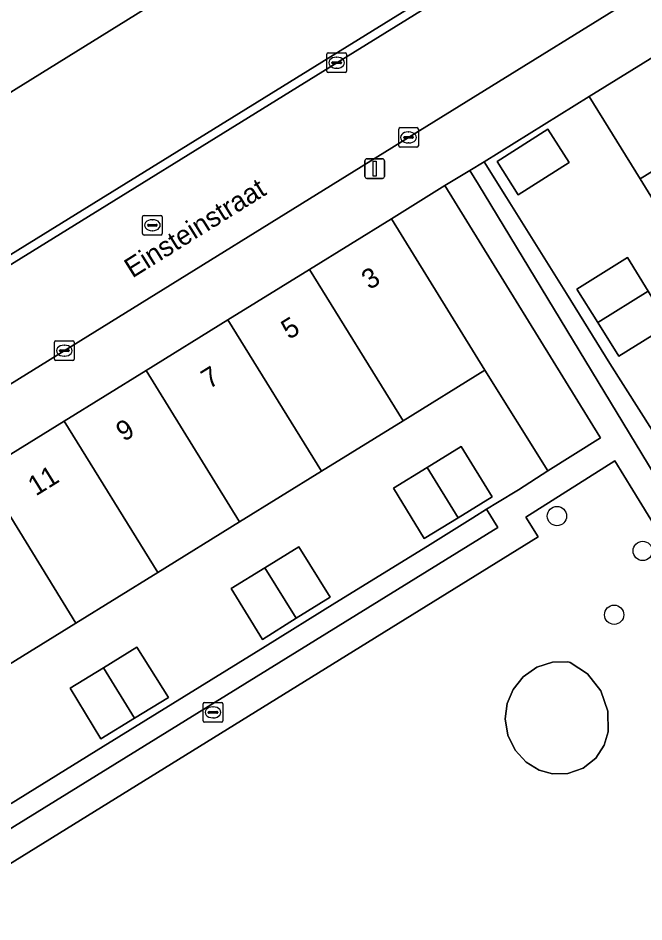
# Model space of a CAD drawing. Extents: x 159888 to 160761, y 384031 to 384750.
# Drawn here: x 160154.85 to 160186.63, y 384561.64 to 384607.52 of the extents above; entities that cross this region are included whole.
import ezdxf

# ---------------------------------------------------------------- set-up
doc = ezdxf.new("R2010")
doc.units = 0
for name, color, linetype in [('IMGEO_Boom', 7, 'Continuous'), ('IMGEO_Erf', 7, 'Continuous'), ('IMGEO_Groenvoorziening', 7, 'Continuous'), ('IMGEO_Kolk', 7, 'Continuous'), ('IMGEO_Lichtmast', 7, 'Continuous'), ('IMGEO_Openbare_ruimte_label', 7, 'Continuous'), ('IMGEO_Pand', 7, 'Continuous'), ('IMGEO_Pand_nummerreeks', 7, 'Continuous'), ('IMGEO_Rijbaan_lokaal_open', 7, 'Continuous'), ('IMGEO_Rioolput', 7, 'Continuous'), ('IMGEO_Terreindeel_onvherhard', 7, 'Continuous'), ('IMGEO_Voetpad_open', 7, 'Continuous')]:
    doc.layers.add(name, color=color, linetype=linetype)

msp = doc.modelspace()

# ---------------------------------------------------------------- linework, layer by layer
at = {"layer": 'IMGEO_Boom'}
for centre in [(160182.218, 384582.245), (160186.573, 384580.476), (160185.121, 384577.235)]:
    msp.add_circle(centre, 0.489, dxfattribs=at)
at = {"layer": 'IMGEO_Erf'}
for points in [[(160137.178, 384619.898), (160101.924, 384598.362), (160110.734, 384584.277), (160114.059, 384578.949), (160127.142, 384586.832), (160189.258, 384625.337)], [(160154.504, 384567.651), (160159.181, 384570.545), (160162.717, 384572.729), (160167.402, 384575.62), (160170.932, 384577.817), (160175.649, 384580.721), (160176.59, 384581.308), (160177.945, 384582.154), (160178.648, 384582.593), (160179.199, 384582.937), (160180.262, 384583.57), (160181.762, 384584.546), (160178.562, 384589.653), (160174.408, 384587.085), (160170.254, 384584.518), (160166.1, 384581.95), (160161.945, 384579.382), (160157.791, 384576.814), (160153.637, 384574.247)]]:
    msp.add_lwpolyline(points, dxfattribs=at)
for points in [[(160201.898, 384574.344), (160199.321, 384578.512), (160196.745, 384582.681), (160194.168, 384586.85), (160191.591, 384591.019), (160189.015, 384595.187), (160186.438, 384599.356), (160183.852, 384603.54), (160178.522, 384600.227), (160179.656, 384598.411), (160182.706, 384593.538), (160184.899, 384589.992), (160187.856, 384585.356), (160190.049, 384581.81), (160192.976, 384577.075), (160195.169, 384573.529), (160198.086, 384568.923), (160200.279, 384565.377), (160201.907, 384562.777), (160207.047, 384566.013), (160204.475, 384570.175)], [(160180.252, 384598.554), (160179.181, 384600.243), (160181.759, 384601.877), (160182.83, 384600.188)], [(160185.358, 384590.358), (160184.289, 384592.064), (160183.219, 384593.769), (160185.792, 384595.375), (160186.841, 384593.664), (160187.905, 384591.929)], [(160173.91, 384583.659), (160175.63, 384584.716), (160177.35, 384585.773), (160178.921, 384583.217), (160177.201, 384582.16), (160175.481, 384581.103)], [(160165.677, 384578.561), (160167.392, 384579.621), (160169.107, 384580.68), (160170.697, 384578.131), (160168.977, 384577.055), (160167.263, 384575.983)], [(160157.492, 384573.501), (160159.189, 384574.542), (160160.887, 384575.582), (160162.484, 384573.035), (160160.759, 384571.98), (160159.059, 384570.94)]]:
    msp.add_lwpolyline(points, close=True, dxfattribs=at)
at = {"layer": 'IMGEO_Groenvoorziening'}
for points in [[(160187.228, 384615.776), (160189.258, 384625.337), (160127.142, 384586.832), (160114.059, 384578.949), (160114.138, 384578.822), (160118.034, 384572.48), (160122.909, 384575.488), (160128.843, 384579.15), (160136.097, 384583.626), (160140.332, 384586.252), (160140.095, 384586.635)], [(160214.717, 384570.75), (160207.047, 384566.013), (160201.907, 384562.777), (160200.279, 384565.377), (160198.086, 384568.923), (160195.169, 384573.529), (160192.976, 384577.075), (160190.049, 384581.81), (160187.856, 384585.356), (160184.899, 384589.992), (160182.706, 384593.538), (160179.656, 384598.411), (160178.522, 384600.227), (160177.796, 384599.792), (160178.233, 384599.071), (160201.865, 384560.132), (160209.103, 384564.601), (160215.907, 384568.818)], [(160176.521, 384599.021), (160173.813, 384597.334), (160178.562, 384589.653), (160181.762, 384584.546), (160184.426, 384586.21), (160184.387, 384586.273)], [(160179.214, 384581.669), (160178.648, 384582.593), (160177.945, 384582.154), (160176.59, 384581.308), (160175.649, 384580.721), (160170.932, 384577.817), (160167.402, 384575.62), (160162.717, 384572.729), (160159.181, 384570.545), (160154.504, 384567.651), (160150.964, 384565.459), (160146.234, 384562.542), (160142.688, 384560.346), (160138.005, 384557.454), (160134.451, 384555.279), (160131.882, 384553.717), (160132.027, 384553.482), (160132.473, 384552.799), (160139.949, 384557.419)], [(160179.72, 384571.131), (160179.591, 384571.95), (160179.687, 384572.723), (160179.987, 384573.442), (160180.505, 384574.088), (160181.203, 384574.568), (160181.992, 384574.821), (160182.771, 384574.844), (160182.834, 384574.835), (160182.894, 384574.814), (160183.766, 384574.239), (160184.444, 384573.373), (160184.804, 384572.334), (160184.815, 384571.29), (160184.615, 384570.612), (160184.186, 384569.963), (160183.543, 384569.455), (160182.771, 384569.18), (160181.993, 384569.161), (160181.312, 384569.351), (160180.647, 384569.758), (160180.088, 384570.369)]]:
    msp.add_lwpolyline(points, close=True, dxfattribs=at)
msp.add_lwpolyline([(160189.322, 384578.257), (160186.066, 384583.561), (160185.149, 384585.056), (160180.644, 384582.188), (160181.266, 384581.183), (160148.281, 384560.789), (160152.94, 384553.3), (160163.406, 384536.375), (160200.868, 384559.503)], dxfattribs=at)
at = {"layer": 'IMGEO_Kolk'}
for p, q in [((160170.606, 384605.758), (160171.458, 384605.758)), ((160170.531, 384604.832), (160170.531, 384605.684)), ((160170.833, 384605.301), (160171.231, 384605.301)), ((160171.019, 384605.538), (160171.044, 384605.538)), ((160171.532, 384605.684), (160171.532, 384604.832)), ((160170.79, 384605.252), (160170.79, 384605.264)), ((160171.228, 384605.215), (160170.83, 384605.215)), ((160171.042, 384604.978), (160171.017, 384604.978)), ((160171.274, 384605.264), (160171.274, 384605.252)), ((160171.458, 384604.758), (160170.606, 384604.758)), ((160174.18, 384601.039), (160174.18, 384601.891)), ((160174.255, 384601.965), (160175.107, 384601.965)), ((160174.668, 384601.745), (160174.693, 384601.745)), ((160175.181, 384601.891), (160175.181, 384601.039)), ((160174.439, 384601.459), (160174.439, 384601.471)), ((160174.877, 384601.422), (160174.479, 384601.422)), ((160174.482, 384601.508), (160174.88, 384601.508)), ((160174.691, 384601.185), (160174.666, 384601.185)), ((160174.923, 384601.471), (160174.923, 384601.459)), ((160175.107, 384600.965), (160174.255, 384600.965)), ((160156.701, 384590.215), (160156.701, 384591.067)), ((160156.776, 384591.141), (160157.628, 384591.141)), ((160157.702, 384591.067), (160157.702, 384590.215)), ((160156.96, 384590.635), (160156.96, 384590.647)), ((160157.003, 384590.684), (160157.401, 384590.684)), ((160157.189, 384590.921), (160157.214, 384590.921)), ((160157.444, 384590.647), (160157.444, 384590.635)), ((160157.398, 384590.598), (160157, 384590.598)), ((160157.212, 384590.361), (160157.187, 384590.361)), ((160157.628, 384590.141), (160156.776, 384590.141)), ((160164.251, 384571.855), (160164.251, 384572.707)), ((160164.326, 384572.781), (160165.178, 384572.781)), ((160165.252, 384572.707), (160165.252, 384571.855)), ((160164.51, 384572.275), (160164.51, 384572.287)), ((160164.553, 384572.324), (160164.951, 384572.324)), ((160164.739, 384572.561), (160164.764, 384572.561)), ((160164.994, 384572.287), (160164.994, 384572.275)), ((160164.948, 384572.238), (160164.55, 384572.238)), ((160164.762, 384572.001), (160164.737, 384572.001)), ((160165.178, 384571.781), (160164.326, 384571.781))]:
    msp.add_line(p, q, dxfattribs=at)
for points in [[(160170.606, 384605.758), (160171.458, 384605.758)], [(160170.531, 384604.832), (160170.531, 384605.684)], [(160171.532, 384605.684), (160171.532, 384604.832)], [(160171.458, 384604.758), (160170.606, 384604.758)], [(160174.18, 384601.039), (160174.18, 384601.891)], [(160174.255, 384601.965), (160175.107, 384601.965)], [(160175.181, 384601.891), (160175.181, 384601.039)], [(160175.107, 384600.965), (160174.255, 384600.965)], [(160156.701, 384590.215), (160156.701, 384591.067)], [(160156.776, 384591.141), (160157.628, 384591.141)], [(160157.702, 384591.067), (160157.702, 384590.215)], [(160157.628, 384590.141), (160156.776, 384590.141)], [(160164.251, 384571.855), (160164.251, 384572.707)], [(160164.326, 384572.781), (160165.178, 384572.781)], [(160165.252, 384572.707), (160165.252, 384571.855)], [(160165.178, 384571.781), (160164.326, 384571.781)]]:
    msp.add_lwpolyline(points, dxfattribs=at)
for centre, radius, start, end in [((160170.608, 384605.682), 0.0765, 91.552, 178.448), ((160170.608, 384605.682), 0.0765, 91.552, 178.448), ((160171.456, 384605.682), 0.0765, 1.552, 88.448), ((160171.456, 384605.682), 0.0765, 1.552, 88.448), ((160170.83, 384605.261), 0.0403, 85.8775, 175.7526), ((160171.235, 384605.263), 0.0386, 1.7309, 96.639), ((160170.608, 384604.834), 0.0765, 181.552, 268.448), ((160170.608, 384604.834), 0.0765, 181.552, 268.448), ((160170.827, 384605.251), 0.0366, 178.938, 274.7102), ((160171.231, 384605.258), 0.043, 264.8664, 352.4533), ((160171.456, 384604.834), 0.0765, 271.552, 358.448), ((160171.456, 384604.834), 0.0765, 271.552, 358.448), ((160174.257, 384601.889), 0.0765, 91.552, 178.448), ((160174.257, 384601.889), 0.0765, 91.552, 178.448), ((160175.105, 384601.889), 0.0765, 1.552, 88.448), ((160175.105, 384601.889), 0.0765, 1.552, 88.448), ((160174.479, 384601.468), 0.0403, 85.8775, 175.7526), ((160174.476, 384601.458), 0.0366, 178.938, 274.7102), ((160174.88, 384601.465), 0.043, 264.8664, 352.4533), ((160174.884, 384601.47), 0.0386, 1.7309, 96.639), ((160174.257, 384601.041), 0.0765, 181.552, 268.448), ((160174.257, 384601.041), 0.0765, 181.552, 268.448), ((160175.105, 384601.041), 0.0765, 271.552, 358.448), ((160175.105, 384601.041), 0.0765, 271.552, 358.448), ((160156.778, 384591.065), 0.0765, 91.552, 178.448), ((160156.778, 384591.065), 0.0765, 91.552, 178.448), ((160157.626, 384591.065), 0.0765, 1.552, 88.448), ((160157.626, 384591.065), 0.0765, 1.552, 88.448), ((160157, 384590.644), 0.0403, 85.8775, 175.7526), ((160156.997, 384590.634), 0.0366, 178.938, 274.7102), ((160157.401, 384590.641), 0.043, 264.8664, 352.4533), ((160157.405, 384590.646), 0.0386, 1.7309, 96.639), ((160156.778, 384590.217), 0.0765, 181.552, 268.448), ((160156.778, 384590.217), 0.0765, 181.552, 268.448), ((160157.626, 384590.217), 0.0765, 271.552, 358.448), ((160157.626, 384590.217), 0.0765, 271.552, 358.448), ((160164.328, 384572.705), 0.0765, 91.552, 178.448), ((160164.328, 384572.705), 0.0765, 91.552, 178.448), ((160165.176, 384572.705), 0.0765, 1.552, 88.448), ((160165.176, 384572.705), 0.0765, 1.552, 88.448), ((160164.55, 384572.284), 0.0403, 85.8775, 175.7526), ((160164.547, 384572.274), 0.0366, 178.938, 274.7102), ((160164.951, 384572.281), 0.043, 264.8664, 352.4533), ((160164.955, 384572.286), 0.0386, 1.7309, 96.639), ((160164.328, 384571.857), 0.0765, 181.552, 268.448), ((160164.328, 384571.857), 0.0765, 181.552, 268.448), ((160165.176, 384571.857), 0.0765, 271.552, 358.448), ((160165.176, 384571.857), 0.0765, 271.552, 358.448)]:
    msp.add_arc(centre, radius, start, end, dxfattribs=at)
for centre, major_axis, ratio, start_param, end_param in [((160171.018, 384605.258), (-0.387, 0.002), 0.722429, 4.712389, 7.853982), ((160171.043, 384605.258), (-0.39, 0.002), 0.717154, 1.570796, 4.712389), ((160174.667, 384601.465), (-0.387, 0.002), 0.722429, 4.712389, 7.853982), ((160174.692, 384601.465), (-0.39, 0.002), 0.717154, 1.570796, 4.712389), ((160157.188, 384590.641), (-0.387, 0.002), 0.722429, 4.712389, 7.853982), ((160157.213, 384590.641), (-0.39, 0.002), 0.717154, 1.570796, 4.712389), ((160164.738, 384572.281), (-0.387, 0.002), 0.722429, 4.712389, 7.853982), ((160164.763, 384572.281), (-0.39, 0.002), 0.717154, 1.570796, 4.712389)]:
    msp.add_ellipse(centre, major_axis=major_axis, ratio=ratio, start_param=start_param, end_param=end_param, dxfattribs=at)
at = {"layer": 'IMGEO_Lichtmast'}
for p, q in [((160172.469, 384599.482), (160172.469, 384600.282)), ((160172.469, 384600.282), (160172.469, 384599.482)), ((160172.569, 384600.382), (160173.359, 384600.382)), ((160173.359, 384600.382), (160172.569, 384600.382)), ((160173.459, 384600.282), (160173.459, 384599.482)), ((160173.459, 384599.482), (160173.459, 384600.282)), ((160173.359, 384599.382), (160172.569, 384599.382)), ((160172.569, 384599.382), (160173.359, 384599.382))]:
    msp.add_line(p, q, dxfattribs=at)
msp.add_lwpolyline([(160172.889, 384600.257), (160173.039, 384600.257), (160173.039, 384599.507), (160172.889, 384599.507), (160172.889, 384600.257)], dxfattribs=at)
for centre, start, end in [((160172.569, 384600.282), 90, 180), ((160172.569, 384600.282), 90, 180), ((160173.359, 384600.282), 0, 90), ((160173.359, 384600.282), 360, 90), ((160172.569, 384599.482), 180, 270), ((160172.569, 384599.482), 180, 270), ((160173.359, 384599.482), 270, 0), ((160173.359, 384599.482), 270, 0)]:
    msp.add_arc(centre, 0.1, start, end, dxfattribs=at)
at = {"layer": 'IMGEO_Pand'}
for points in [[(160191.506, 384608.256), (160183.852, 384603.54), (160186.438, 384599.356), (160194.085, 384604.089)], [(160194.085, 384604.089), (160186.438, 384599.356), (160189.015, 384595.187), (160196.664, 384599.921)], [(160180.252, 384598.554), (160182.83, 384600.188), (160181.759, 384601.877), (160179.181, 384600.243)], [(160173.813, 384597.334), (160169.659, 384594.767), (160174.408, 384587.085), (160178.562, 384589.653)], [(160183.219, 384593.769), (160184.289, 384592.064), (160186.841, 384593.664), (160185.792, 384595.375)], [(160169.659, 384594.767), (160165.505, 384592.2), (160170.254, 384584.518), (160174.408, 384587.085)], [(160186.841, 384593.664), (160184.289, 384592.064), (160185.358, 384590.358), (160187.905, 384591.929)], [(160165.505, 384592.2), (160161.35, 384589.633), (160166.1, 384581.95), (160170.254, 384584.518)], [(160161.35, 384589.633), (160157.196, 384587.066), (160161.945, 384579.382), (160166.1, 384581.95)], [(160157.196, 384587.066), (160153.041, 384584.499), (160157.791, 384576.814), (160161.945, 384579.382)], [(160177.35, 384585.773), (160175.63, 384584.716), (160177.201, 384582.16), (160178.921, 384583.217)], [(160175.63, 384584.716), (160173.91, 384583.659), (160175.481, 384581.103), (160177.201, 384582.16)], [(160153.041, 384584.499), (160148.887, 384581.931), (160153.637, 384574.247), (160157.791, 384576.814)], [(160169.107, 384580.68), (160167.392, 384579.621), (160168.977, 384577.055), (160170.697, 384578.131)], [(160167.392, 384579.621), (160165.677, 384578.561), (160167.263, 384575.983), (160168.977, 384577.055)], [(160160.887, 384575.582), (160159.189, 384574.542), (160160.759, 384571.98), (160162.484, 384573.035)], [(160159.189, 384574.542), (160157.492, 384573.501), (160159.059, 384570.94), (160160.759, 384571.98)]]:
    msp.add_lwpolyline(points, close=True, dxfattribs=at)
at = {"layer": 'IMGEO_Rijbaan_lokaal_open'}
for points in [[(160189.063, 384616.395), (160187.103, 384615.185), (160186.109, 384614.571), (160171.032, 384605.258), (160153.576, 384594.465), (160140.332, 384586.252), (160136.097, 384583.626), (160128.843, 384579.15), (160122.909, 384575.488), (160118.034, 384572.48), (160116.393, 384571.466)], [(160119.095, 384567.099), (160125.73, 384571.163), (160142.314, 384581.429), (160157.202, 384590.641), (160174.681, 384601.465), (160189.904, 384610.881), (160190.488, 384611.242), (160192.716, 384612.554)]]:
    msp.add_lwpolyline(points, dxfattribs=at)
at = {"layer": 'IMGEO_Rioolput'}
for p, q in [((160161.249, 384597.51), (160162.101, 384597.51)), ((160161.174, 384596.584), (160161.174, 384597.436)), ((160161.476, 384597.053), (160161.874, 384597.053)), ((160161.662, 384597.29), (160161.687, 384597.29)), ((160162.175, 384597.436), (160162.175, 384596.584)), ((160161.433, 384597.004), (160161.433, 384597.016)), ((160161.871, 384596.967), (160161.473, 384596.967)), ((160161.685, 384596.73), (160161.66, 384596.73)), ((160161.917, 384597.016), (160161.917, 384597.004)), ((160162.101, 384596.51), (160161.249, 384596.51))]:
    msp.add_line(p, q, dxfattribs=at)
for points in [[(160161.249, 384597.51), (160162.101, 384597.51)], [(160161.174, 384596.584), (160161.174, 384597.436)], [(160162.175, 384597.436), (160162.175, 384596.584)], [(160162.101, 384596.51), (160161.249, 384596.51)]]:
    msp.add_lwpolyline(points, dxfattribs=at)
for centre, radius, start, end in [((160161.251, 384597.434), 0.0765, 91.552, 178.448), ((160161.251, 384597.434), 0.0765, 91.552, 178.448), ((160162.099, 384597.434), 0.0765, 1.552, 88.448), ((160162.099, 384597.434), 0.0765, 1.552, 88.448), ((160161.473, 384597.013), 0.0403, 85.8775, 175.7526), ((160161.878, 384597.015), 0.0386, 1.7309, 96.639), ((160161.251, 384596.586), 0.0765, 181.552, 268.448), ((160161.251, 384596.586), 0.0765, 181.552, 268.448), ((160161.47, 384597.003), 0.0366, 178.938, 274.7102), ((160161.874, 384597.01), 0.043, 264.8664, 352.4533), ((160162.099, 384596.586), 0.0765, 271.552, 358.448), ((160162.099, 384596.586), 0.0765, 271.552, 358.448)]:
    msp.add_arc(centre, radius, start, end, dxfattribs=at)
for centre, major_axis, ratio, start_param, end_param in [((160161.661, 384597.01), (-0.387, 0.002), 0.722429, 4.712389, 7.853982), ((160161.686, 384597.01), (-0.39, 0.002), 0.717154, 1.570796, 4.712389)]:
    msp.add_ellipse(centre, major_axis=major_axis, ratio=ratio, start_param=start_param, end_param=end_param, dxfattribs=at)
at = {"layer": 'IMGEO_Terreindeel_onvherhard'}
msp.add_lwpolyline([(160181.992, 384574.821), (160181.203, 384574.568), (160180.505, 384574.088), (160179.987, 384573.442), (160179.687, 384572.723), (160179.591, 384571.95), (160179.72, 384571.131), (160180.088, 384570.369), (160180.647, 384569.758), (160181.312, 384569.351), (160181.993, 384569.161), (160182.771, 384569.18), (160183.543, 384569.455), (160184.186, 384569.963), (160184.615, 384570.612), (160184.815, 384571.29), (160184.804, 384572.334), (160184.444, 384573.373), (160183.766, 384574.239), (160182.894, 384574.814), (160182.834, 384574.835), (160182.771, 384574.844)], close=True, dxfattribs=at)
at = {"layer": 'IMGEO_Voetpad_open'}
for points in [[(160190.512, 384643.774), (160188.418, 384647.232), (160188.044, 384647.685), (160187.632, 384648.103), (160187.184, 384648.483), (160186.703, 384648.821), (160186.194, 384649.114), (160185.662, 384649.361), (160185.513, 384649.415), (160183.001, 384647.819), (160183.718, 384646.606), (160188.748, 384638.307), (160189.435, 384637.152), (160191.151, 384634.267), (160190.632, 384631.811), (160189.258, 384625.337), (160187.228, 384615.776), (160140.095, 384586.635), (160140.332, 384586.252), (160153.576, 384594.465), (160171.032, 384605.258), (160186.109, 384614.571), (160187.103, 384615.185), (160189.063, 384616.395)], [(160192.716, 384612.554), (160190.488, 384611.242), (160189.904, 384610.881), (160174.681, 384601.465), (160157.202, 384590.641), (160142.314, 384581.429), (160125.73, 384571.163), (160119.095, 384567.099)], [(160128.118, 384569.089), (160132.271, 384571.659), (160136.424, 384574.229), (160138.335, 384575.411), (160140.578, 384576.797), (160144.732, 384579.364), (160148.887, 384581.931), (160153.041, 384584.499), (160157.196, 384587.066), (160161.35, 384589.633), (160165.505, 384592.2), (160169.659, 384594.767), (160173.813, 384597.334), (160176.521, 384599.021), (160177.796, 384599.792), (160178.522, 384600.227), (160183.852, 384603.54), (160191.506, 384608.256)], [(160201.865, 384560.132), (160178.233, 384599.071), (160177.796, 384599.792), (160176.521, 384599.021), (160184.387, 384586.273), (160184.426, 384586.21), (160181.762, 384584.546), (160180.262, 384583.57), (160179.199, 384582.937), (160178.648, 384582.593), (160179.214, 384581.669), (160139.949, 384557.419), (160132.473, 384552.799), (160133.251, 384551.488), (160147, 384559.992), (160156.159, 384545.179), (160169.806, 384523.173), (160171.445, 384520.533), (160172.677, 384521.294), (160170.426, 384524.933), (160164.199, 384535.04), (160201.679, 384558.218)]]:
    msp.add_lwpolyline(points, dxfattribs=at)
msp.add_lwpolyline([(160196.17, 384567.098), (160200.122, 384560.709), (160200.868, 384559.503), (160163.406, 384536.375), (160152.94, 384553.3), (160148.281, 384560.789), (160181.266, 384581.183), (160180.644, 384582.188), (160185.149, 384585.056), (160186.066, 384583.561), (160189.322, 384578.257)], close=True, dxfattribs=at)

# ---------------------------------------------------------------- texts
at = {"layer": 'IMGEO_Openbare_ruimte_label'}
msp.add_text('Einsteinstraat', height=1, rotation=32.0054, dxfattribs=at).set_placement((160160.658, 384594.302))
at = {"layer": 'IMGEO_Pand_nummerreeks'}
for s, p in [('3', (160172.696, 384593.705)), ('5', (160168.613, 384591.181)), ('7', (160164.553, 384588.673)), ('9', (160160.226, 384585.999)), ('11', (160155.755, 384583.237))]:
    msp.add_text(s, height=1, rotation=31.7132, dxfattribs=at).set_placement(p)

doc.saveas('drawing.dxf')
